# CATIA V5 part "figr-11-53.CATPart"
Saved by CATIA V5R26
Part number: Part1
Bounding box of the stored display mesh (mm): x -70 to 82, y -87.905 to 70, z 0 to 79.806
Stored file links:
  E:\_Deepak\CATIA\CATIA V5-6R2016_Deepak\Resources\Part files\Partfiles\c11_catia_v5_6r2016_prt\figr-11-53.CATPart
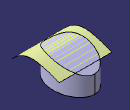
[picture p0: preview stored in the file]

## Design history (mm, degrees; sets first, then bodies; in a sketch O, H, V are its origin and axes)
Set1
  Extrude1: Element1 Sketch2, Lim1 82, Lim2 70, Direction yz-plane
Body1 (main body)
  Sketch1 on xy-plane, origin (0, 0, 0), H (1, 0, 0), V (0, 1, 0)
    ellipse A1 centre (0, 0) semi-axes 70, 50 rotation 90
    point P1 (50, 0)
    coincidence: P1 H, A1 P1
  Pad1: profile Sketch1, direction (0, 0, 1), length 84
  Split1: SplitPlane Extrude1
  Sketch2 on yz-plane, origin (0, 0, 0), H (0, 1, 0), V (0, 0, 1)
    spline S1 through (-87.9047, 49.8062) (-27.9047, 79.8062) (23.1382, 69.0456) (49.2374, 59.3792)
